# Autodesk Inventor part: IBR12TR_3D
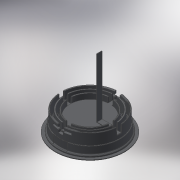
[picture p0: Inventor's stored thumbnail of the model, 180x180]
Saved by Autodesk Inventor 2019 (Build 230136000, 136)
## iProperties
Created: 2020-04
Part Number: IBR12TR_3D
Material: Generic
Document SubType Name: Modeling
Designer: EL
Density: 1 g/cm^3
Appearance: Default
Author: EL
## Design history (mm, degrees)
derived "IGBR12TR-XX-V.iam"
node "Solid148.ipt:1"
body "Srf1"
node "P110008_01-Piastrino UL LBXS RING 12x.ipt:1"
node "Spacer for Blade R UL.ipt:1"
node "PA90.ipt:1"
node "Solid21_1_test.ipt:1"
node "IGBR12TR-XX-V.iam_Bodies"
